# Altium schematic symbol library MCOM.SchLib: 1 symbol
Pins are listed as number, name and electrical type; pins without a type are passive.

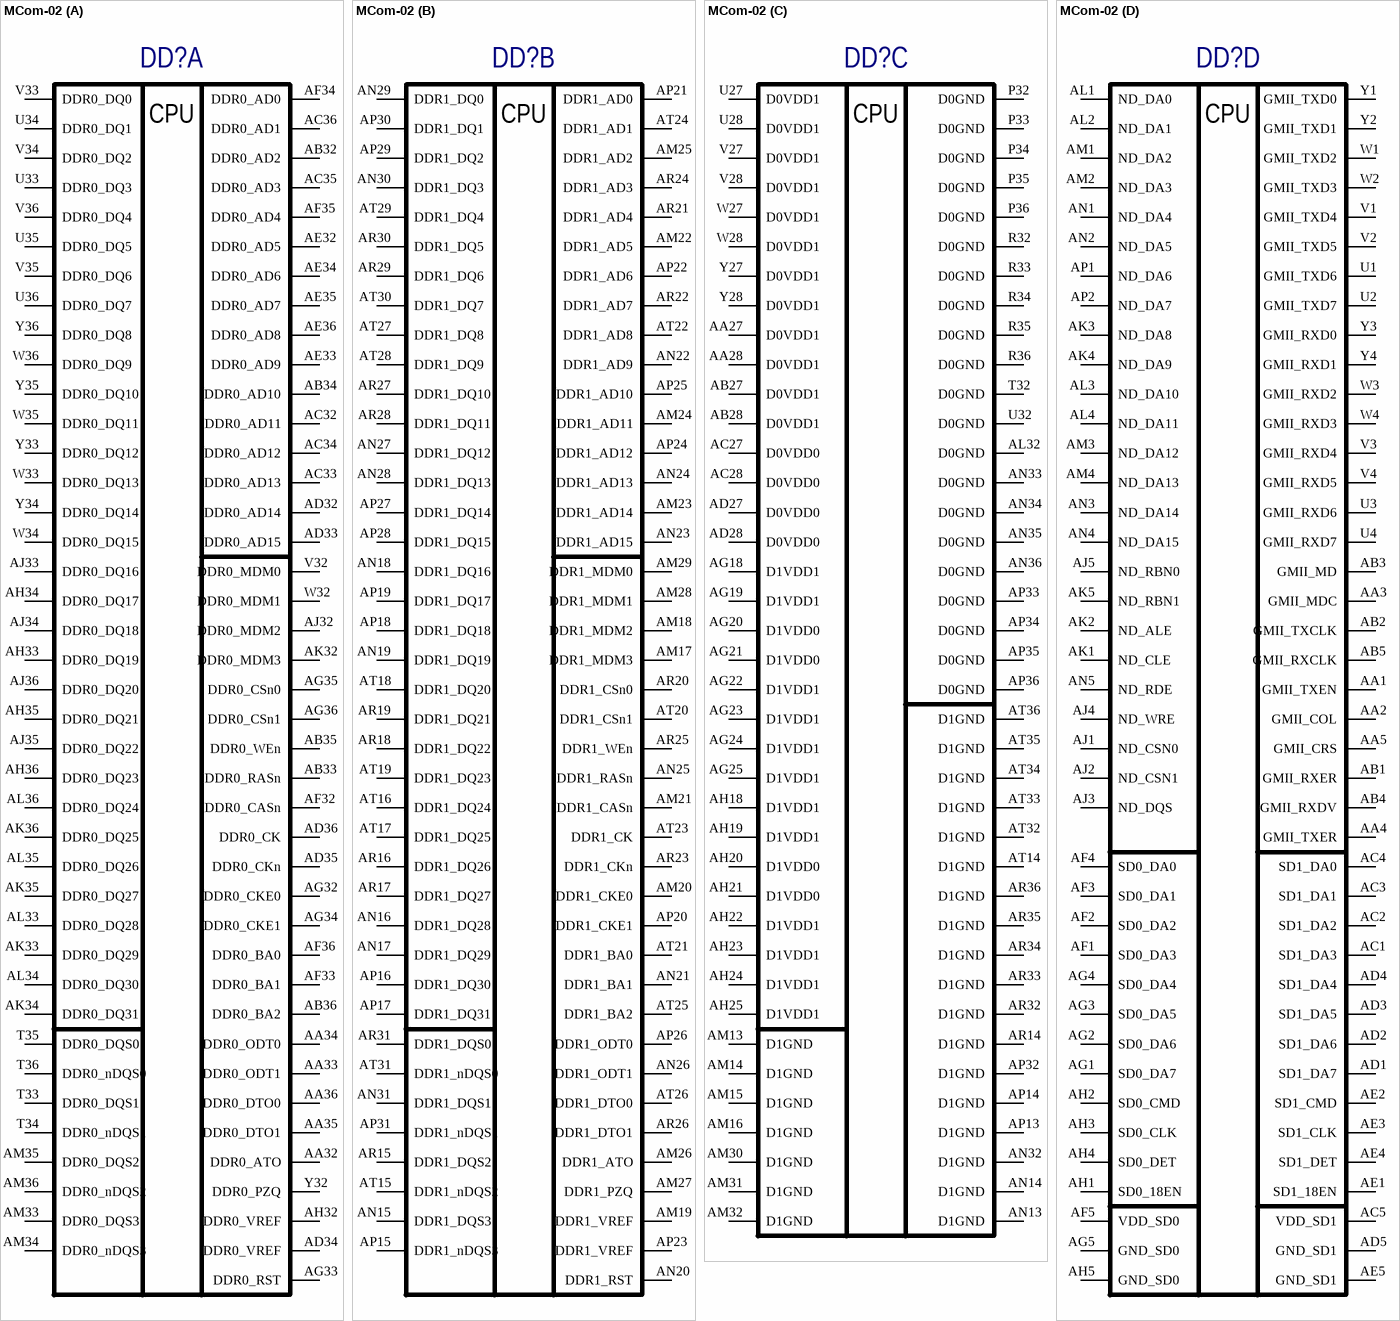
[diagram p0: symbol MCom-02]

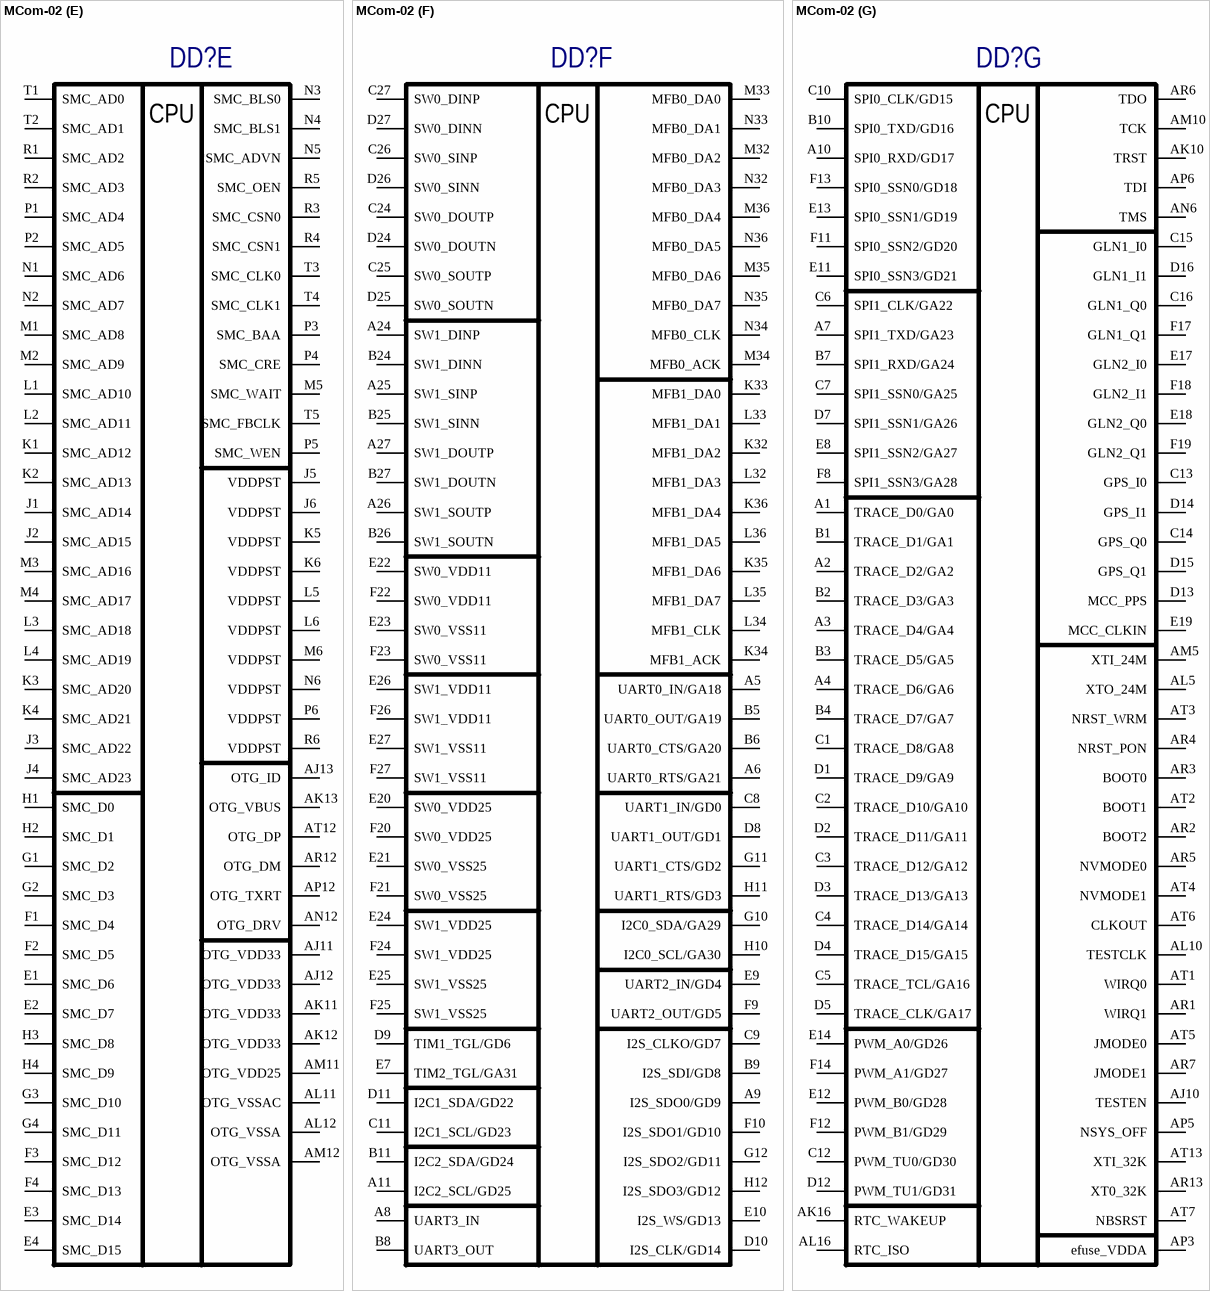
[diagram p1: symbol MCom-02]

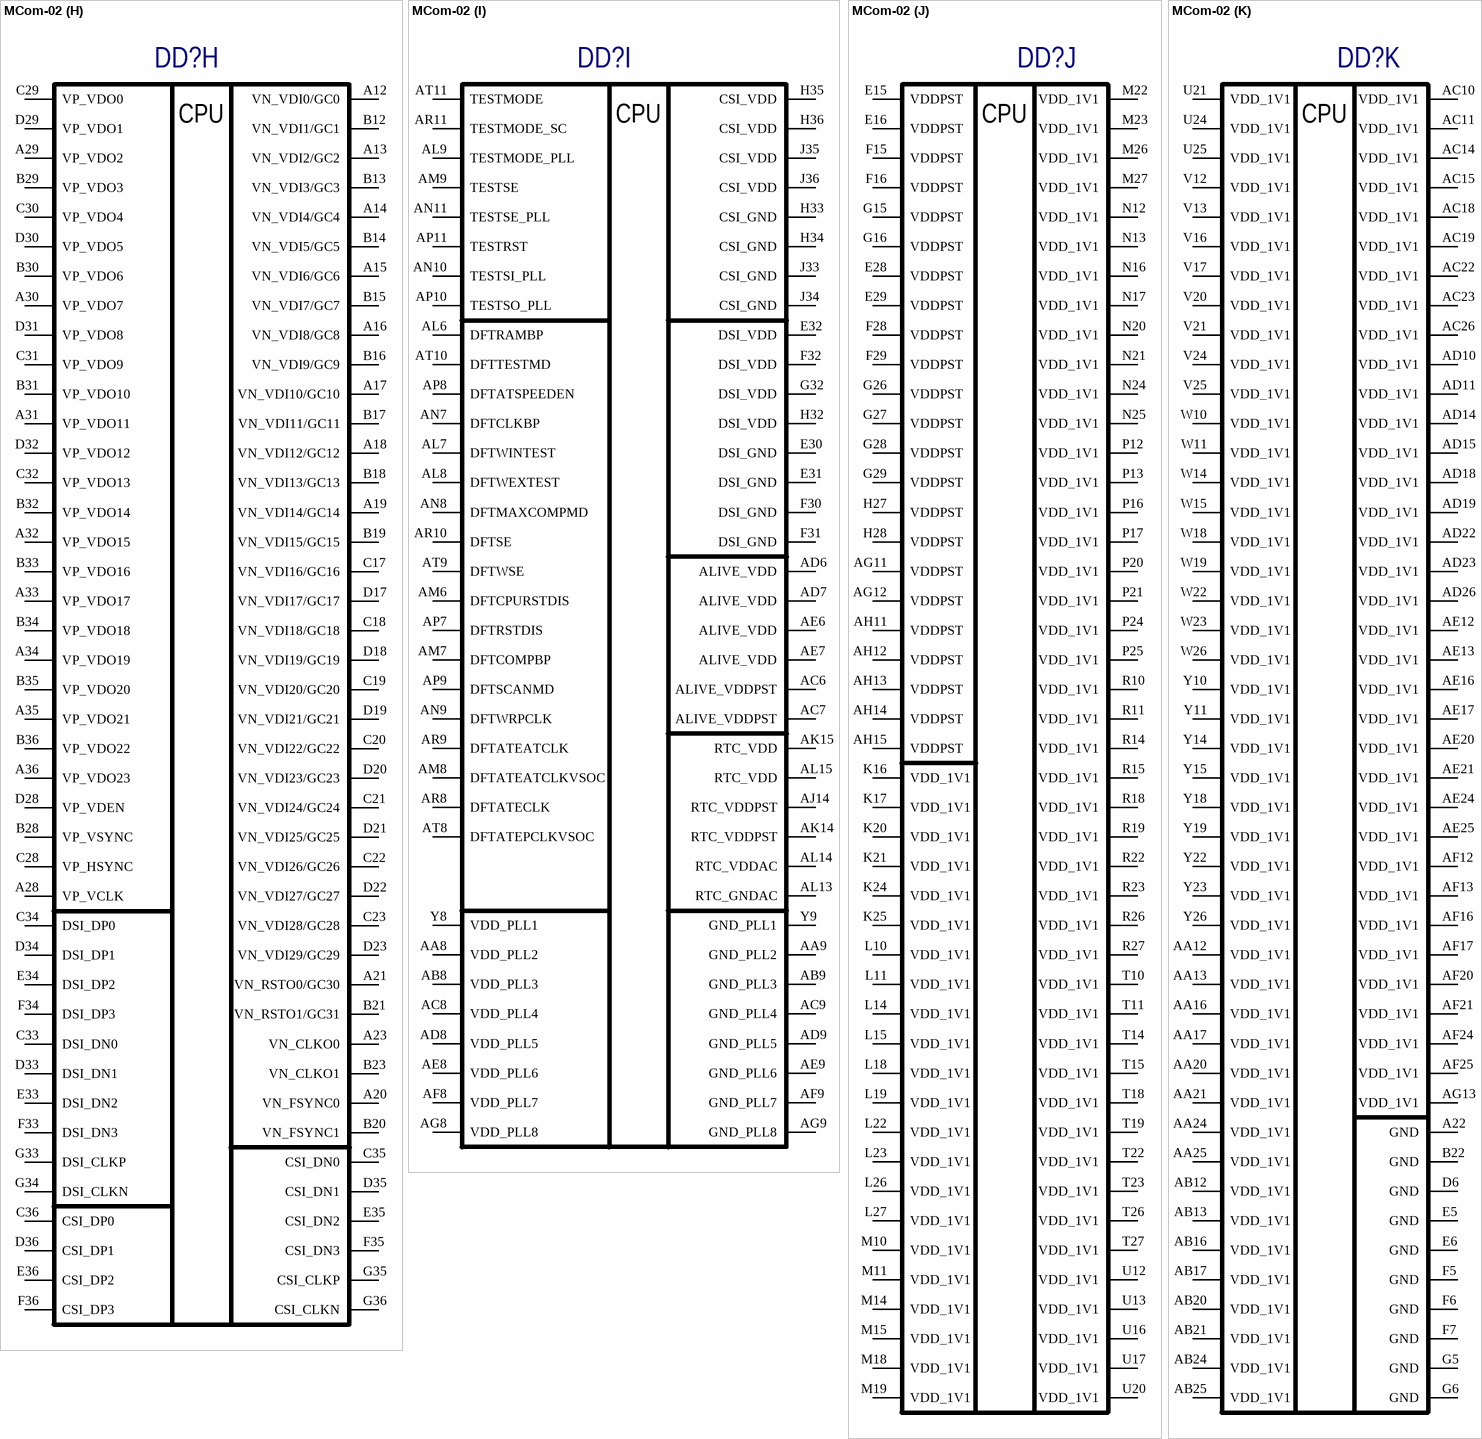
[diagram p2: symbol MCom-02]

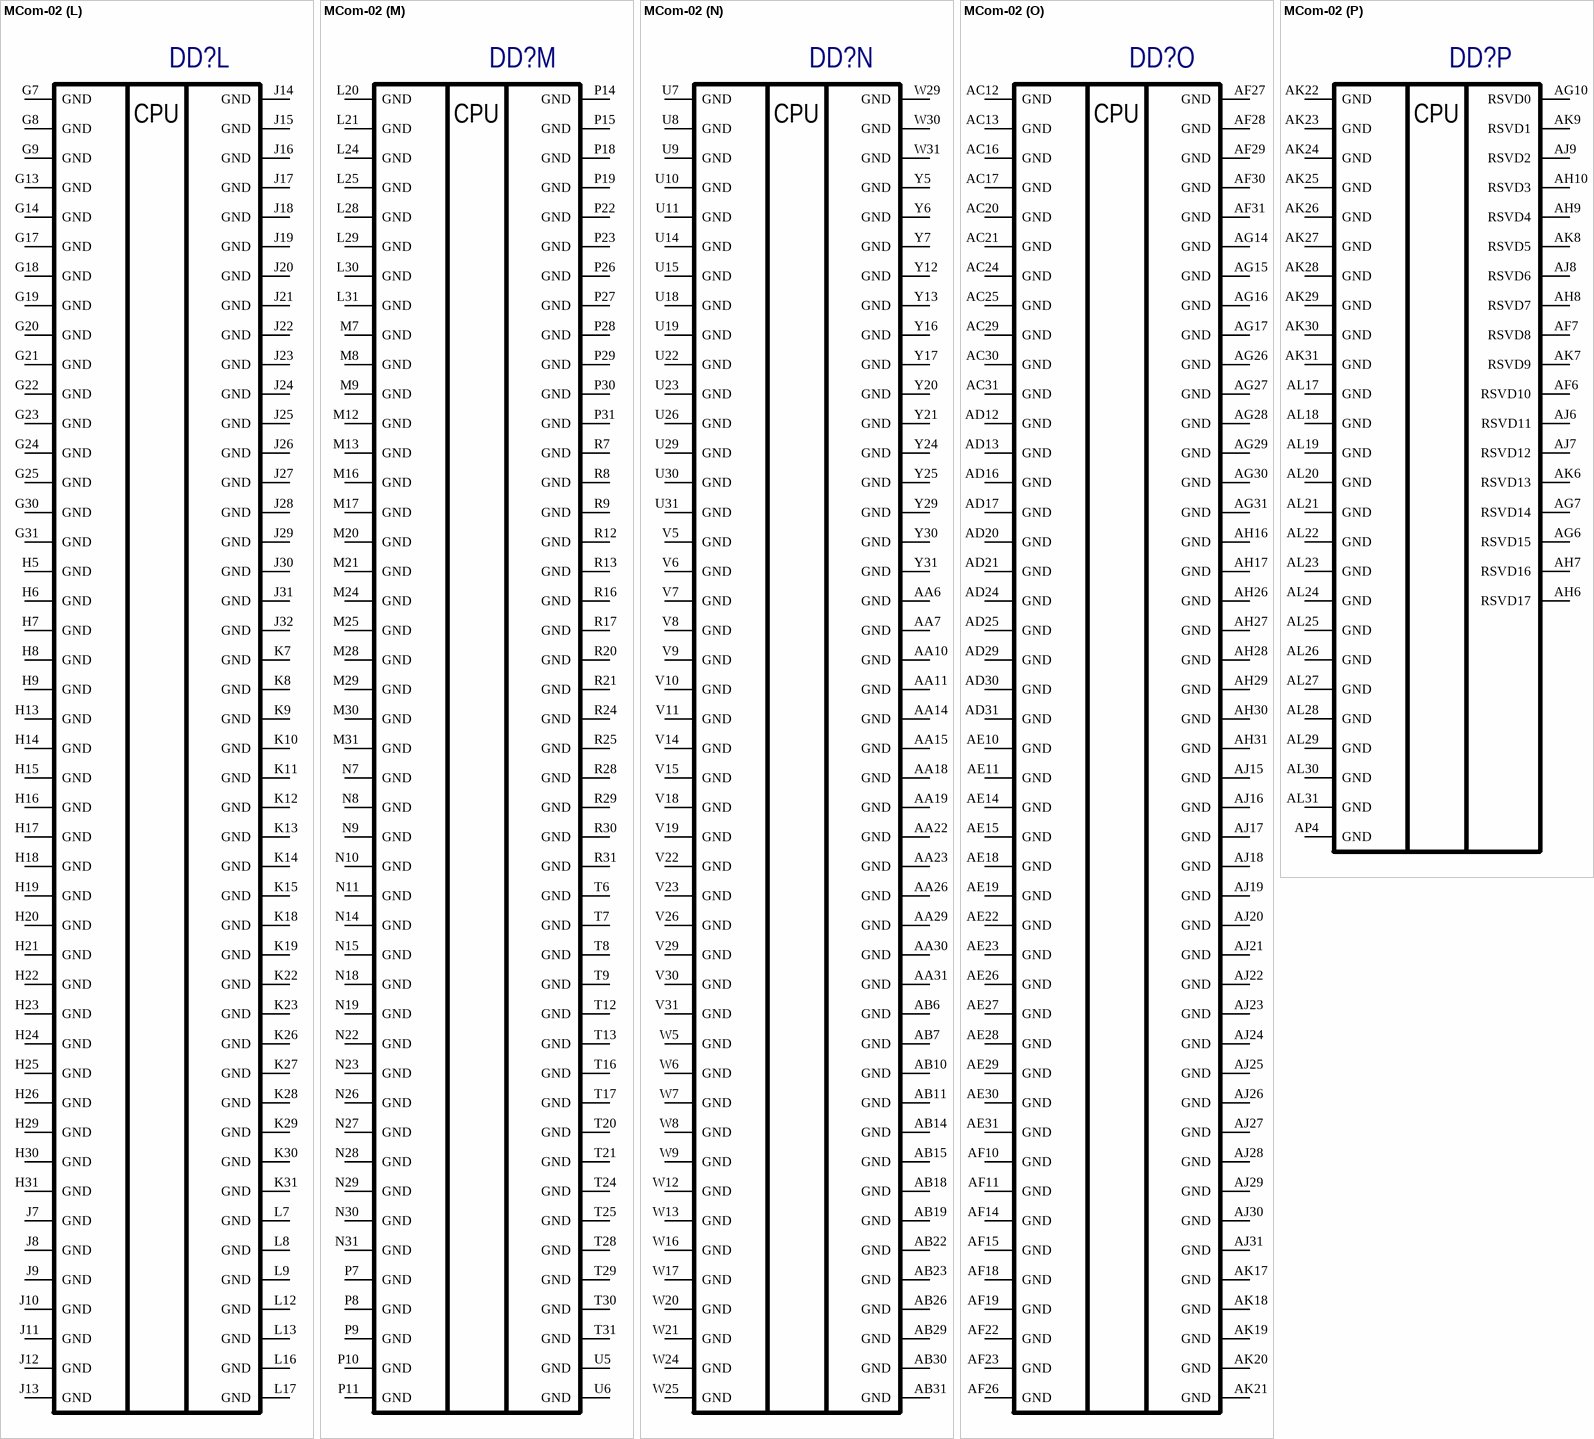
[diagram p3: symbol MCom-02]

## MCom-02
designator DD?, comment MCom-02.1  (value not drawn)
Процессор; Note: Elvees; _Type: IC
footprint BGA1296(36x36pin_19x19mm)
part A pins: AA32 DDR0_ATO "Byte Low Enable", AA33 DDR0_ODT1 "Byte Low Enable", AA34 DDR0_ODT0 "Byte Low Enable", AA35 DDR0_DTO1 "Byte Low Enable", AA36 DDR0_DTO0 "Byte Low Enable", AB32 DDR0_AD2, AB33 DDR0_RASn "Byte Low Enable", AB34 DDR0_AD10 "Output Enables", AB35 DDR0_WEn "Byte Low Enable", AB36 DDR0_BA2 "Byte Low Enable", AC32 DDR0_AD11 "Write Enable", AC33 DDR0_AD13 "Byte Low Enable", AC34 DDR0_AD12 "Byte High Enable", AC35 DDR0_AD3, AC36 DDR0_AD1, AD32 DDR0_AD14 "Byte Low Enable", AD33 DDR0_AD15 "Byte Low Enable", AD34 DDR0_VREF "Byte Low Enable", AD35 DDR0_CKn "Byte Low Enable", AD36 DDR0_CK "Byte Low Enable", AE32 DDR0_AD5, AE33 DDR0_AD9, AE34 DDR0_AD6, AE35 DDR0_AD7, AE36 DDR0_AD8, AF32 DDR0_CASn "Byte Low Enable", AF33 DDR0_BA1 "Byte Low Enable", AF34 DDR0_AD0, AF35 DDR0_AD4, AF36 DDR0_BA0 "Byte Low Enable", AG32 DDR0_CKE0 "Byte Low Enable", AG33 DDR0_RST "Byte Low Enable", AG34 DDR0_CKE1 "Byte Low Enable", AG35 DDR0_CSn0 "Byte Low Enable", AG36 DDR0_CSn1 "Byte Low Enable", AH32 DDR0_VREF "Byte Low Enable", AH33 DDR0_DQ19, AH34 DDR0_DQ17, AH35 DDR0_DQ21, AH36 DDR0_DQ23, AJ32 DDR0_MDM2 "Byte Low Enable", AJ33 DDR0_DQ16, AJ34 DDR0_DQ18, AJ35 DDR0_DQ22, AJ36 DDR0_DQ20, AK32 DDR0_MDM3 "Byte Low Enable", AK33 DDR0_DQ29, AK34 DDR0_DQ31, AK35 DDR0_DQ27, AK36 DDR0_DQ25, AL33 DDR0_DQ28, AL34 DDR0_DQ30, AL35 DDR0_DQ26, AL36 DDR0_DQ24, AM33 DDR0_DQS3, AM34 DDR0_nDQS3, AM35 DDR0_DQS2, AM36 DDR0_nDQS2, T33 DDR0_DQS1, T34 DDR0_nDQS1, T35 DDR0_DQS0, T36 DDR0_nDQS0, U33 DDR0_DQ3, U34 DDR0_DQ1, U35 DDR0_DQ5, U36 DDR0_DQ7, V32 DDR0_MDM0 "Byte Low Enable", V33 DDR0_DQ0, V34 DDR0_DQ2, V35 DDR0_DQ6, V36 DDR0_DQ4, W32 DDR0_MDM1 "Byte Low Enable", W33 DDR0_DQ13, W34 DDR0_DQ15, W35 DDR0_DQ11, W36 DDR0_DQ9, Y32 DDR0_PZQ "Byte Low Enable", Y33 DDR0_DQ12, Y34 DDR0_DQ14, Y35 DDR0_DQ10, Y36 DDR0_DQ8
part B pins: AM17 DDR1_MDM3 "Byte Low Enable", AM18 DDR1_MDM2 "Byte Low Enable", AM19 DDR1_VREF "Byte Low Enable", AM20 DDR1_CKE0 "Byte Low Enable", AM21 DDR1_CASn "Byte Low Enable", AM22 DDR1_AD5, AM23 DDR1_AD14 "Byte Low Enable", AM24 DDR1_AD11 "Write Enable", AM25 DDR1_AD2, AM26 DDR1_ATO "Byte Low Enable", AM27 DDR1_PZQ "Byte Low Enable", AM28 DDR1_MDM1 "Byte Low Enable", AM29 DDR1_MDM0 "Byte Low Enable", AN15 DDR1_DQS3, AN16 DDR1_DQ28, AN17 DDR1_DQ29, AN18 DDR1_DQ16, AN19 DDR1_DQ19, AN20 DDR1_RST "Byte Low Enable", AN21 DDR1_BA1 "Byte Low Enable", AN22 DDR1_AD9, AN23 DDR1_AD15 "Byte Low Enable", AN24 DDR1_AD13 "Byte Low Enable", AN25 DDR1_RASn "Byte Low Enable", AN26 DDR1_ODT1 "Byte Low Enable", AN27 DDR1_DQ12, AN28 DDR1_DQ13, AN29 DDR1_DQ0, AN30 DDR1_DQ3, AN31 DDR1_DQS1, AP15 DDR1_nDQS3, AP16 DDR1_DQ30, AP17 DDR1_DQ31, AP18 DDR1_DQ18, AP19 DDR1_DQ17, AP20 DDR1_CKE1 "Byte Low Enable", AP21 DDR1_AD0, AP22 DDR1_AD6, AP23 DDR1_VREF "Byte Low Enable", AP24 DDR1_AD12 "Byte High Enable", AP25 DDR1_AD10 "Output Enables", AP26 DDR1_ODT0 "Byte Low Enable", AP27 DDR1_DQ14, AP28 DDR1_DQ15, AP29 DDR1_DQ2, AP30 DDR1_DQ1, AP31 DDR1_nDQS1, AR15 DDR1_DQS2, AR16 DDR1_DQ26, AR17 DDR1_DQ27, AR18 DDR1_DQ22, AR19 DDR1_DQ21, AR20 DDR1_CSn0 "Byte Low Enable", AR21 DDR1_AD4, AR22 DDR1_AD7, AR23 DDR1_CKn "Byte Low Enable", AR24 DDR1_AD3, AR25 DDR1_WEn "Byte Low Enable", AR26 DDR1_DTO1 "Byte Low Enable", AR27 DDR1_DQ10, AR28 DDR1_DQ11, AR29 DDR1_DQ6, AR30 DDR1_DQ5, AR31 DDR1_DQS0, AT15 DDR1_nDQS2, AT16 DDR1_DQ24, AT17 DDR1_DQ25, AT18 DDR1_DQ20, AT19 DDR1_DQ23, AT20 DDR1_CSn1 "Byte Low Enable", AT21 DDR1_BA0 "Byte Low Enable", AT22 DDR1_AD8, AT23 DDR1_CK "Byte Low Enable", AT24 DDR1_AD1, AT25 DDR1_BA2 "Byte Low Enable", AT26 DDR1_DTO0 "Byte Low Enable", AT27 DDR1_DQ8, AT28 DDR1_DQ9, AT29 DDR1_DQ4, AT30 DDR1_DQ7, AT31 DDR1_nDQS0
part C pins: AA27 D0VDD1, AA28 D0VDD1, AB27 D0VDD1, AB28 D0VDD1, AC27 D0VDD0, AC28 D0VDD0, AD27 D0VDD0, AD28 D0VDD0, AG18 D1VDD1, AG19 D1VDD1, AG20 D1VDD0, AG21 D1VDD0, AG22 D1VDD1, AG23 D1VDD1, AG24 D1VDD1, AG25 D1VDD1, AH18 D1VDD1, AH19 D1VDD1, AH20 D1VDD0, AH21 D1VDD0, AH22 D1VDD1, AH23 D1VDD1, AH24 D1VDD1, AH25 D1VDD1, AL32 D0GND, AM13 D1GND, AM14 D1GND, AM15 D1GND, AM16 D1GND, AM30 D1GND, AM31 D1GND, AM32 D1GND, AN13 D1GND, AN14 D1GND, AN32 D1GND, AN33 D0GND, AN34 D0GND, AN35 D0GND, AN36 D0GND, AP13 D1GND, AP14 D1GND, AP32 D1GND, AP33 D0GND, AP34 D0GND, AP35 D0GND, AP36 D0GND, AR14 D1GND, AR32 D1GND, AR33 D1GND, AR34 D1GND, AR35 D1GND, AR36 D1GND, AT14 D1GND, AT32 D1GND, AT33 D1GND, AT34 D1GND, AT35 D1GND, AT36 D1GND, P32 D0GND, P33 D0GND, P34 D0GND, P35 D0GND, P36 D0GND, R32 D0GND, R33 D0GND, R34 D0GND, R35 D0GND, R36 D0GND, T32 D0GND, U27 D0VDD1, U28 D0VDD1, U32 D0GND, V27 D0VDD1, V28 D0VDD1, W27 D0VDD1, W28 D0VDD1, Y27 D0VDD1, Y28 D0VDD1
part D pins: AA1 GMII_TXEN, AA2 GMII_COL, AA3 GMII_MDC, AA4 GMII_TXER, AA5 GMII_CRS, AB1 GMII_RXER, AB2 GMII_TXCLK, AB3 GMII_MD, AB4 GMII_RXDV, AB5 GMII_RXCLK, AC1 SD1_DA3, AC2 SD1_DA2, AC3 SD1_DA1, AC4 SD1_DA0, AC5 VDD_SD1, AD1 SD1_DA7, AD2 SD1_DA6, AD3 SD1_DA5, AD4 SD1_DA4, AD5 GND_SD1, AE1 SD1_18EN, AE2 SD1_CMD, AE3 SD1_CLK, AE4 SD1_DET, AE5 GND_SD1, AF1 SD0_DA3, AF2 SD0_DA2, AF3 SD0_DA1, AF4 SD0_DA0, AF5 VDD_SD0, AG1 SD0_DA7, AG2 SD0_DA6, AG3 SD0_DA5, AG4 SD0_DA4, AG5 GND_SD0, AH1 SD0_18EN, AH2 SD0_CMD, AH3 SD0_CLK, AH4 SD0_DET, AH5 GND_SD0, AJ1 ND_CSN0, AJ2 ND_CSN1, AJ3 ND_DQS, AJ4 ND_WRE, AJ5 ND_RBN0, AK1 ND_CLE, AK2 ND_ALE, AK3 ND_DA8, AK4 ND_DA9, AK5 ND_RBN1, AL1 ND_DA0, AL2 ND_DA1, AL3 ND_DA10, AL4 ND_DA11, AM1 ND_DA2, AM2 ND_DA3, AM3 ND_DA12, AM4 ND_DA13, AN1 ND_DA4, AN2 ND_DA5, AN3 ND_DA14, AN4 ND_DA15, AN5 ND_RDE, AP1 ND_DA6, AP2 ND_DA7, U1 GMII_TXD6, U2 GMII_TXD7, U3 GMII_RXD6, U4 GMII_RXD7, V1 GMII_TXD4, V2 GMII_TXD5, V3 GMII_RXD4, V4 GMII_RXD5, W1 GMII_TXD2, W2 GMII_TXD3, W3 GMII_RXD2, W4 GMII_RXD3, Y1 GMII_TXD0, Y2 GMII_TXD1, Y3 GMII_RXD0, Y4 GMII_RXD1
part E pins: AJ11 OTG_VDD33, AJ12 OTG_VDD33, AJ13 OTG_ID, AK11 OTG_VDD33, AK12 OTG_VDD33, AK13 OTG_VBUS, AL11 OTG_VSSAC, AL12 OTG_VSSA, AM11 OTG_VDD25, AM12 OTG_VSSA, AN12 OTG_DRV, AP12 OTG_TXRT, AR12 OTG_DM, AT12 OTG_DP, E1 SMC_D6, E2 SMC_D7, E3 SMC_D14, E4 SMC_D15, F1 SMC_D4, F2 SMC_D5, F3 SMC_D12, F4 SMC_D13, G1 SMC_D2, G2 SMC_D3, G3 SMC_D10, G4 SMC_D11, H1 SMC_D0, H2 SMC_D1, H3 SMC_D8, H4 SMC_D9, J1 SMC_AD14, J2 SMC_AD15, J3 SMC_AD22, J4 SMC_AD23, J5 VDDPST, J6 VDDPST, K1 SMC_AD12, K2 SMC_AD13, K3 SMC_AD20, K4 SMC_AD21, K5 VDDPST, K6 VDDPST, L1 SMC_AD10, L2 SMC_AD11, L3 SMC_AD18, L4 SMC_AD19, L5 VDDPST, L6 VDDPST, M1 SMC_AD8, M2 SMC_AD9, M3 SMC_AD16, M4 SMC_AD17, M5 SMC_WAIT, M6 VDDPST, N1 SMC_AD6, N2 SMC_AD7, N3 SMC_BLS0, N4 SMC_BLS1, N5 SMC_ADVN, N6 VDDPST, P1 SMC_AD4, P2 SMC_AD5, P3 SMC_BAA, P4 SMC_CRE, P5 SMC_WEN, P6 VDDPST, R1 SMC_AD2, R2 SMC_AD3, R3 SMC_CSN0, R4 SMC_CSN1, R5 SMC_OEN, R6 VDDPST, T1 SMC_AD0, T2 SMC_AD1, T3 SMC_CLK0, T4 SMC_CLK1, T5 SMC_FBCLK
part F pins: A5 UART0_IN/GA18, A6 UART0_RTS/GA21, A8 UART3_IN, A9 I2S_SDO0/GD9, A11 I2C2_SCL/GD25, A24 SW1_DINP, A25 SW1_SINP, A26 SW1_SOUTP, A27 SW1_DOUTP, B5 UART0_OUT/GA19, B6 UART0_CTS/GA20, B8 UART3_OUT, B9 I2S_SDI/GD8, B11 I2C2_SDA/GD24, B24 SW1_DINN, B25 SW1_SINN, B26 SW1_SOUTN, B27 SW1_DOUTN, C8 UART1_IN/GD0, C9 I2S_CLKO/GD7, C11 I2C1_SCL/GD23, C24 SW0_DOUTP, C25 SW0_SOUTP, C26 SW0_SINP, C27 SW0_DINP, D8 UART1_OUT/GD1, D9 TIM1_TGL/GD6, D10 I2S_CLK/GD14, D11 I2C1_SDA/GD22, D24 SW0_DOUTN, D25 SW0_SOUTN, D26 SW0_SINN, D27 SW0_DINN, E7 TIM2_TGL/GA31, E9 UART2_IN/GD4, E10 I2S_WS/GD13, E20 SW0_VDD25, E21 SW0_VSS25, E22 SW0_VDD11, E23 SW0_VSS11, E24 SW1_VDD25, E25 SW1_VSS25, E26 SW1_VDD11, E27 SW1_VSS11, F9 UART2_OUT/GD5, F10 I2S_SDO1/GD10, F20 SW0_VDD25, F21 SW0_VSS25, F22 SW0_VDD11, F23 SW0_VSS11, F24 SW1_VDD25, F25 SW1_VSS25, F26 SW1_VDD11, F27 SW1_VSS11, G10 I2C0_SDA/GA29, G11 UART1_CTS/GD2, G12 I2S_SDO2/GD11, H10 I2C0_SCL/GA30, H11 UART1_RTS/GD3, H12 I2S_SDO3/GD12, K32 MFB1_DA2, K33 MFB1_DA0, K34 MFB1_ACK, K35 MFB1_DA6, K36 MFB1_DA4, L32 MFB1_DA3, L33 MFB1_DA1, L34 MFB1_CLK, L35 MFB1_DA7, L36 MFB1_DA5, M32 MFB0_DA2, M33 MFB0_DA0, M34 MFB0_ACK, M35 MFB0_DA6, M36 MFB0_DA4, N32 MFB0_DA3, N33 MFB0_DA1, N34 MFB0_CLK, N35 MFB0_DA7, N36 MFB0_DA5
part G pins: A1 TRACE_D0/GA0, A2 TRACE_D2/GA2, A3 TRACE_D4/GA4, A4 TRACE_D6/GA6, A7 SPI1_TXD/GA23, A10 SPI0_RXD/GD17, AJ10 TESTEN, AK10 TRST, AK16 RTC_WAKEUP, AL5 XTO_24M, AL10 TESTCLK, AL16 RTC_ISO, AM5 XTI_24M, AM10 TCK, AN6 TMS, AP3 efuse_VDDA, AP5 NSYS_OFF, AP6 TDI, AR1 WIRQ1, AR2 BOOT2, AR3 BOOT0, AR4 NRST_PON, AR5 NVMODE0, AR6 TDO, AR7 JMODE1, AR13 XT0_32K, AT1 WIRQ0, AT2 BOOT1, AT3 NRST_WRM, AT4 NVMODE1, AT5 JMODE0, AT6 CLKOUT, AT7 NBSRST, AT13 XTI_32K, B1 TRACE_D1/GA1, B2 TRACE_D3/GA3, B3 TRACE_D5/GA5, B4 TRACE_D7/GA7, B7 SPI1_RXD/GA24, B10 SPI0_TXD/GD16, C1 TRACE_D8/GA8, C2 TRACE_D10/GA10, C3 TRACE_D12/GA12, C4 TRACE_D14/GA14, C5 TRACE_TCL/GA16, C6 SPI1_CLK/GA22, C7 SPI1_SSN0/GA25, C10 SPI0_CLK/GD15, C12 PWM_TU0/GD30, C13 GPS_I0, C14 GPS_Q0, C15 GLN1_I0, C16 GLN1_Q0, D1 TRACE_D9/GA9, D2 TRACE_D11/GA11, D3 TRACE_D13/GA13, D4 TRACE_D15/GA15, D5 TRACE_CLK/GA17, D7 SPI1_SSN1/GA26, D12 PWM_TU1/GD31, D13 MCC_PPS, D14 GPS_I1, D15 GPS_Q1, D16 GLN1_I1, E8 SPI1_SSN2/GA27, E11 SPI0_SSN3/GD21, E12 PWM_B0/GD28, E13 SPI0_SSN1/GD19, E14 PWM_A0/GD26, E17 GLN2_I0, E18 GLN2_Q0, E19 MCC_CLKIN, F8 SPI1_SSN3/GA28, F11 SPI0_SSN2/GD20, F12 PWM_B1/GD29, F13 SPI0_SSN0/GD18, F14 PWM_A1/GD27, F17 GLN1_Q1, F18 GLN2_I1, F19 GLN2_Q1
part H pins: A12 VN_VDI0/GC0, A13 VN_VDI2/GC2, A14 VN_VDI4/GC4, A15 VN_VDI6/GC6, A16 VN_VDI8/GC8, A17 VN_VDI10/GC10, A18 VN_VDI12/GC12, A19 VN_VDI14/GC14, A20 VN_FSYNC0, A21 VN_RSTO0/GC30, A23 VN_CLKO0, A28 VP_VCLK, A29 VP_VDO2, A30 VP_VDO7, A31 VP_VDO11, A32 VP_VDO15, A33 VP_VDO17, A34 VP_VDO19, A35 VP_VDO21, A36 VP_VDO23, B12 VN_VDI1/GC1, B13 VN_VDI3/GC3, B14 VN_VDI5/GC5, B15 VN_VDI7/GC7, B16 VN_VDI9/GC9, B17 VN_VDI11/GC11, B18 VN_VDI13/GC13, B19 VN_VDI15/GC15, B20 VN_FSYNC1, B21 VN_RSTO1/GC31, B23 VN_CLKO1, B28 VP_VSYNC, B29 VP_VDO3, B30 VP_VDO6, B31 VP_VDO10, B32 VP_VDO14, B33 VP_VDO16, B34 VP_VDO18, B35 VP_VDO20, B36 VP_VDO22, C17 VN_VDI16/GC16, C18 VN_VDI18/GC18, C19 VN_VDI20/GC20, C20 VN_VDI22/GC22, C21 VN_VDI24/GC24, C22 VN_VDI26/GC26, C23 VN_VDI28/GC28, C28 VP_HSYNC, C29 VP_VDO0, C30 VP_VDO4, C31 VP_VDO9, C32 VP_VDO13, C33 DSI_DN0, C34 DSI_DP0, C35 CSI_DN0, C36 CSI_DP0, D17 VN_VDI17/GC17, D18 VN_VDI19/GC19, D19 VN_VDI21/GC21, D20 VN_VDI23/GC23, D21 VN_VDI25/GC25, D22 VN_VDI27/GC27, D23 VN_VDI29/GC29, D28 VP_VDEN, D29 VP_VDO1, D30 VP_VDO5, D31 VP_VDO8, D32 VP_VDO12, D33 DSI_DN1, D34 DSI_DP1, D35 CSI_DN1, D36 CSI_DP1, E33 DSI_DN2, E34 DSI_DP2, E35 CSI_DN2, E36 CSI_DP2, F33 DSI_DN3, F34 DSI_DP3, F35 CSI_DN3, F36 CSI_DP3, G33 DSI_CLKP, G34 DSI_CLKN, G35 CSI_CLKP, G36 CSI_CLKN
part I pins: AA8 VDD_PLL2, AA9 GND_PLL2, AB8 VDD_PLL3, AB9 GND_PLL3, AC6 ALIVE_VDDPST, AC7 ALIVE_VDDPST, AC8 VDD_PLL4, AC9 GND_PLL4, AD6 ALIVE_VDD, AD7 ALIVE_VDD, AD8 VDD_PLL5, AD9 GND_PLL5, AE6 ALIVE_VDD, AE7 ALIVE_VDD, AE8 VDD_PLL6, AE9 GND_PLL6, AF8 VDD_PLL7, AF9 GND_PLL7, AG8 VDD_PLL8, AG9 GND_PLL8, AJ14 RTC_VDDPST, AK14 RTC_VDDPST, AK15 RTC_VDD, AL6 DFTRAMBP, AL7 DFTWINTEST, AL8 DFTWEXTEST, AL9 TESTMODE_PLL, AL13 RTC_GNDAC, AL14 RTC_VDDAC, AL15 RTC_VDD, AM6 DFTCPURSTDIS, AM7 DFTCOMPBP, AM8 DFTATEATCLKVSOC, AM9 TESTSE, AN7 DFTCLKBP, AN8 DFTMAXCOMPMD, AN9 DFTWRPCLK, AN10 TESTSI_PLL, AN11 TESTSE_PLL, AP7 DFTRSTDIS, AP8 DFTATSPEEDEN, AP9 DFTSCANMD, AP10 TESTSO_PLL, AP11 TESTRST, AR8 DFTATECLK, AR9 DFTATEATCLK, AR10 DFTSE, AR11 TESTMODE_SC, AT8 DFTATEPCLKVSOC, AT9 DFTWSE, AT10 DFTTESTMD, AT11 TESTMODE, E30 DSI_GND, E31 DSI_GND, E32 DSI_VDD, F30 DSI_GND, F31 DSI_GND, F32 DSI_VDD, G32 DSI_VDD, H32 DSI_VDD, H33 CSI_GND, H34 CSI_GND, H35 CSI_VDD, H36 CSI_VDD, J33 CSI_GND, J34 CSI_GND, J35 CSI_VDD, J36 CSI_VDD, Y8 VDD_PLL1, Y9 GND_PLL1
part J pins: AG11 VDDPST, AG12 VDDPST, AH11 VDDPST, AH12 VDDPST, AH13 VDDPST, AH14 VDDPST, AH15 VDDPST, E15 VDDPST, E16 VDDPST, E28 VDDPST, E29 VDDPST, F15 VDDPST, F16 VDDPST, F28 VDDPST, F29 VDDPST, G15 VDDPST, G16 VDDPST, G26 VDDPST, G27 VDDPST, G28 VDDPST, G29 VDDPST, H27 VDDPST, H28 VDDPST, K16 VDD_1V1, K17 VDD_1V1, K20 VDD_1V1, K21 VDD_1V1, K24 VDD_1V1, K25 VDD_1V1, L10 VDD_1V1, L11 VDD_1V1, L14 VDD_1V1, L15 VDD_1V1, L18 VDD_1V1, L19 VDD_1V1, L22 VDD_1V1, L23 VDD_1V1, L26 VDD_1V1, L27 VDD_1V1, M10 VDD_1V1, M11 VDD_1V1, M14 VDD_1V1, M15 VDD_1V1, M18 VDD_1V1, M19 VDD_1V1, M22 VDD_1V1, M23 VDD_1V1, M26 VDD_1V1, M27 VDD_1V1, N12 VDD_1V1, N13 VDD_1V1, N16 VDD_1V1, N17 VDD_1V1, N20 VDD_1V1, N21 VDD_1V1, N24 VDD_1V1, N25 VDD_1V1, P12 VDD_1V1, P13 VDD_1V1, P16 VDD_1V1, P17 VDD_1V1, P20 VDD_1V1, P21 VDD_1V1, P24 VDD_1V1, P25 VDD_1V1, R10 VDD_1V1, R11 VDD_1V1, R14 VDD_1V1, R15 VDD_1V1, R18 VDD_1V1, R19 VDD_1V1, R22 VDD_1V1, R23 VDD_1V1, R26 VDD_1V1, R27 VDD_1V1, T10 VDD_1V1, T11 VDD_1V1, T14 VDD_1V1, T15 VDD_1V1, T18 VDD_1V1, T19 VDD_1V1, T22 VDD_1V1, T23 VDD_1V1, T26 VDD_1V1, T27 VDD_1V1, U12 VDD_1V1, U13 VDD_1V1, U16 VDD_1V1, U17 VDD_1V1, U20 VDD_1V1
part K pins: A22 GND, AA12 VDD_1V1, AA13 VDD_1V1, AA16 VDD_1V1, AA17 VDD_1V1, AA20 VDD_1V1, AA21 VDD_1V1, AA24 VDD_1V1, AA25 VDD_1V1, AB12 VDD_1V1, AB13 VDD_1V1, AB16 VDD_1V1, AB17 VDD_1V1, AB20 VDD_1V1, AB21 VDD_1V1, AB24 VDD_1V1, AB25 VDD_1V1, AC10 VDD_1V1, AC11 VDD_1V1, AC14 VDD_1V1, AC15 VDD_1V1, AC18 VDD_1V1, AC19 VDD_1V1, AC22 VDD_1V1, AC23 VDD_1V1, AC26 VDD_1V1, AD10 VDD_1V1, AD11 VDD_1V1, AD14 VDD_1V1, AD15 VDD_1V1, AD18 VDD_1V1, AD19 VDD_1V1, AD22 VDD_1V1, AD23 VDD_1V1, AD26 VDD_1V1, AE12 VDD_1V1, AE13 VDD_1V1, AE16 VDD_1V1, AE17 VDD_1V1, AE20 VDD_1V1, AE21 VDD_1V1, AE24 VDD_1V1, AE25 VDD_1V1, AF12 VDD_1V1, AF13 VDD_1V1, AF16 VDD_1V1, AF17 VDD_1V1, AF20 VDD_1V1, AF21 VDD_1V1, AF24 VDD_1V1, AF25 VDD_1V1, AG13 VDD_1V1, B22 GND, D6 GND, E5 GND, E6 GND, F5 GND, F6 GND, F7 GND, G5 GND, G6 GND, U21 VDD_1V1, U24 VDD_1V1, U25 VDD_1V1, V12 VDD_1V1, V13 VDD_1V1, V16 VDD_1V1, V17 VDD_1V1, V20 VDD_1V1, V21 VDD_1V1, V24 VDD_1V1, V25 VDD_1V1, W10 VDD_1V1, W11 VDD_1V1, W14 VDD_1V1, W15 VDD_1V1, W18 VDD_1V1, W19 VDD_1V1, W22 VDD_1V1, W23 VDD_1V1, W26 VDD_1V1, Y10 VDD_1V1, Y11 VDD_1V1, Y14 VDD_1V1, Y15 VDD_1V1, Y18 VDD_1V1, Y19 VDD_1V1, Y22 VDD_1V1, Y23 VDD_1V1, Y26 VDD_1V1
part L pins: G7 GND, G8 GND, G9 GND, G13 GND, G14 GND, G17 GND, G18 GND, G19 GND, G20 GND, G21 GND, G22 GND, G23 GND, G24 GND, G25 GND, G30 GND, G31 GND, H5 GND, H6 GND, H7 GND, H8 GND, H9 GND, H13 GND, H14 GND, H15 GND, H16 GND, H17 GND, H18 GND, H19 GND, H20 GND, H21 GND, H22 GND, H23 GND, H24 GND, H25 GND, H26 GND, H29 GND, H30 GND, H31 GND, J7 GND, J8 GND, J9 GND, J10 GND, J11 GND, J12 GND, J13 GND, J14 GND, J15 GND, J16 GND, J17 GND, J18 GND, J19 GND, J20 GND, J21 GND, J22 GND, J23 GND, J24 GND, J25 GND, J26 GND, J27 GND, J28 GND, J29 GND, J30 GND, J31 GND, J32 GND, K7 GND, K8 GND, K9 GND, K10 GND, K11 GND, K12 GND, K13 GND, K14 GND, K15 GND, K18 GND, K19 GND, K22 GND, K23 GND, K26 GND, K27 GND, K28 GND, K29 GND, K30 GND, K31 GND, L7 GND, L8 GND, L9 GND, L12 GND, L13 GND, L16 GND, L17 GND
part M pins: L20 GND, L21 GND, L24 GND, L25 GND, L28 GND, L29 GND, L30 GND, L31 GND, M7 GND, M8 GND, M9 GND, M12 GND, M13 GND, M16 GND, M17 GND, M20 GND, M21 GND, M24 GND, M25 GND, M28 GND, M29 GND, M30 GND, M31 GND, N7 GND, N8 GND, N9 GND, N10 GND, N11 GND, N14 GND, N15 GND, N18 GND, N19 GND, N22 GND, N23 GND, N26 GND, N27 GND, N28 GND, N29 GND, N30 GND, N31 GND, P7 GND, P8 GND, P9 GND, P10 GND, P11 GND, P14 GND, P15 GND, P18 GND, P19 GND, P22 GND, P23 GND, P26 GND, P27 GND, P28 GND, P29 GND, P30 GND, P31 GND, R7 GND, R8 GND, R9 GND, R12 GND, R13 GND, R16 GND, R17 GND, R20 GND, R21 GND, R24 GND, R25 GND, R28 GND, R29 GND, R30 GND, R31 GND, T6 GND, T7 GND, T8 GND, T9 GND, T12 GND, T13 GND, T16 GND, T17 GND, T20 GND, T21 GND, T24 GND, T25 GND, T28 GND, T29 GND, T30 GND, T31 GND, U5 GND, U6 GND
part N pins: AA6 GND, AA7 GND, AA10 GND, AA11 GND, AA14 GND, AA15 GND, AA18 GND, AA19 GND, AA22 GND, AA23 GND, AA26 GND, AA29 GND, AA30 GND, AA31 GND, AB6 GND, AB7 GND, AB10 GND, AB11 GND, AB14 GND, AB15 GND, AB18 GND, AB19 GND, AB22 GND, AB23 GND, AB26 GND, AB29 GND, AB30 GND, AB31 GND, U7 GND, U8 GND, U9 GND, U10 GND, U11 GND, U14 GND, U15 GND, U18 GND, U19 GND, U22 GND, U23 GND, U26 GND, U29 GND, U30 GND, U31 GND, V5 GND, V6 GND, V7 GND, V8 GND, V9 GND, V10 GND, V11 GND, V14 GND, V15 GND, V18 GND, V19 GND, V22 GND, V23 GND, V26 GND, V29 GND, V30 GND, V31 GND, W5 GND, W6 GND, W7 GND, W8 GND, W9 GND, W12 GND, W13 GND, W16 GND, W17 GND, W20 GND, W21 GND, W24 GND, W25 GND, W29 GND, W30 GND, W31 GND, Y5 GND, Y6 GND, Y7 GND, Y12 GND, Y13 GND, Y16 GND, Y17 GND, Y20 GND, Y21 GND, Y24 GND, Y25 GND, Y29 GND, Y30 GND, Y31 GND
part O pins: AC12 GND, AC13 GND, AC16 GND, AC17 GND, AC20 GND, AC21 GND, AC24 GND, AC25 GND, AC29 GND, AC30 GND, AC31 GND, AD12 GND, AD13 GND, AD16 GND, AD17 GND, AD20 GND, AD21 GND, AD24 GND, AD25 GND, AD29 GND, AD30 GND, AD31 GND, AE10 GND, AE11 GND, AE14 GND, AE15 GND, AE18 GND, AE19 GND, AE22 GND, AE23 GND, AE26 GND, AE27 GND, AE28 GND, AE29 GND, AE30 GND, AE31 GND, AF10 GND, AF11 GND, AF14 GND, AF15 GND, AF18 GND, AF19 GND, AF22 GND, AF23 GND, AF26 GND, AF27 GND, AF28 GND, AF29 GND, AF30 GND, AF31 GND, AG14 GND, AG15 GND, AG16 GND, AG17 GND, AG26 GND, AG27 GND, AG28 GND, AG29 GND, AG30 GND, AG31 GND, AH16 GND, AH17 GND, AH26 GND, AH27 GND, AH28 GND, AH29 GND, AH30 GND, AH31 GND, AJ15 GND, AJ16 GND, AJ17 GND, AJ18 GND, AJ19 GND, AJ20 GND, AJ21 GND, AJ22 GND, AJ23 GND, AJ24 GND, AJ25 GND, AJ26 GND, AJ27 GND, AJ28 GND, AJ29 GND, AJ30 GND, AJ31 GND, AK17 GND, AK18 GND, AK19 GND, AK20 GND, AK21 GND
part P pins: AF6 RSVD10, AF7 RSVD8, AG6 RSVD15, AG7 RSVD14, AG10 RSVD0, AH6 RSVD17, AH7 RSVD16, AH8 RSVD7, AH9 RSVD4, AH10 RSVD3, AJ6 RSVD11, AJ7 RSVD12, AJ8 RSVD6, AJ9 RSVD2, AK6 RSVD13, AK7 RSVD9, AK8 RSVD5, AK9 RSVD1, AK22 GND, AK23 GND, AK24 GND, AK25 GND, AK26 GND, AK27 GND, AK28 GND, AK29 GND, AK30 GND, AK31 GND, AL17 GND, AL18 GND, AL19 GND, AL20 GND, AL21 GND, AL22 GND, AL23 GND, AL24 GND, AL25 GND, AL26 GND, AL27 GND, AL28 GND, AL29 GND, AL30 GND, AL31 GND, AP4 GND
